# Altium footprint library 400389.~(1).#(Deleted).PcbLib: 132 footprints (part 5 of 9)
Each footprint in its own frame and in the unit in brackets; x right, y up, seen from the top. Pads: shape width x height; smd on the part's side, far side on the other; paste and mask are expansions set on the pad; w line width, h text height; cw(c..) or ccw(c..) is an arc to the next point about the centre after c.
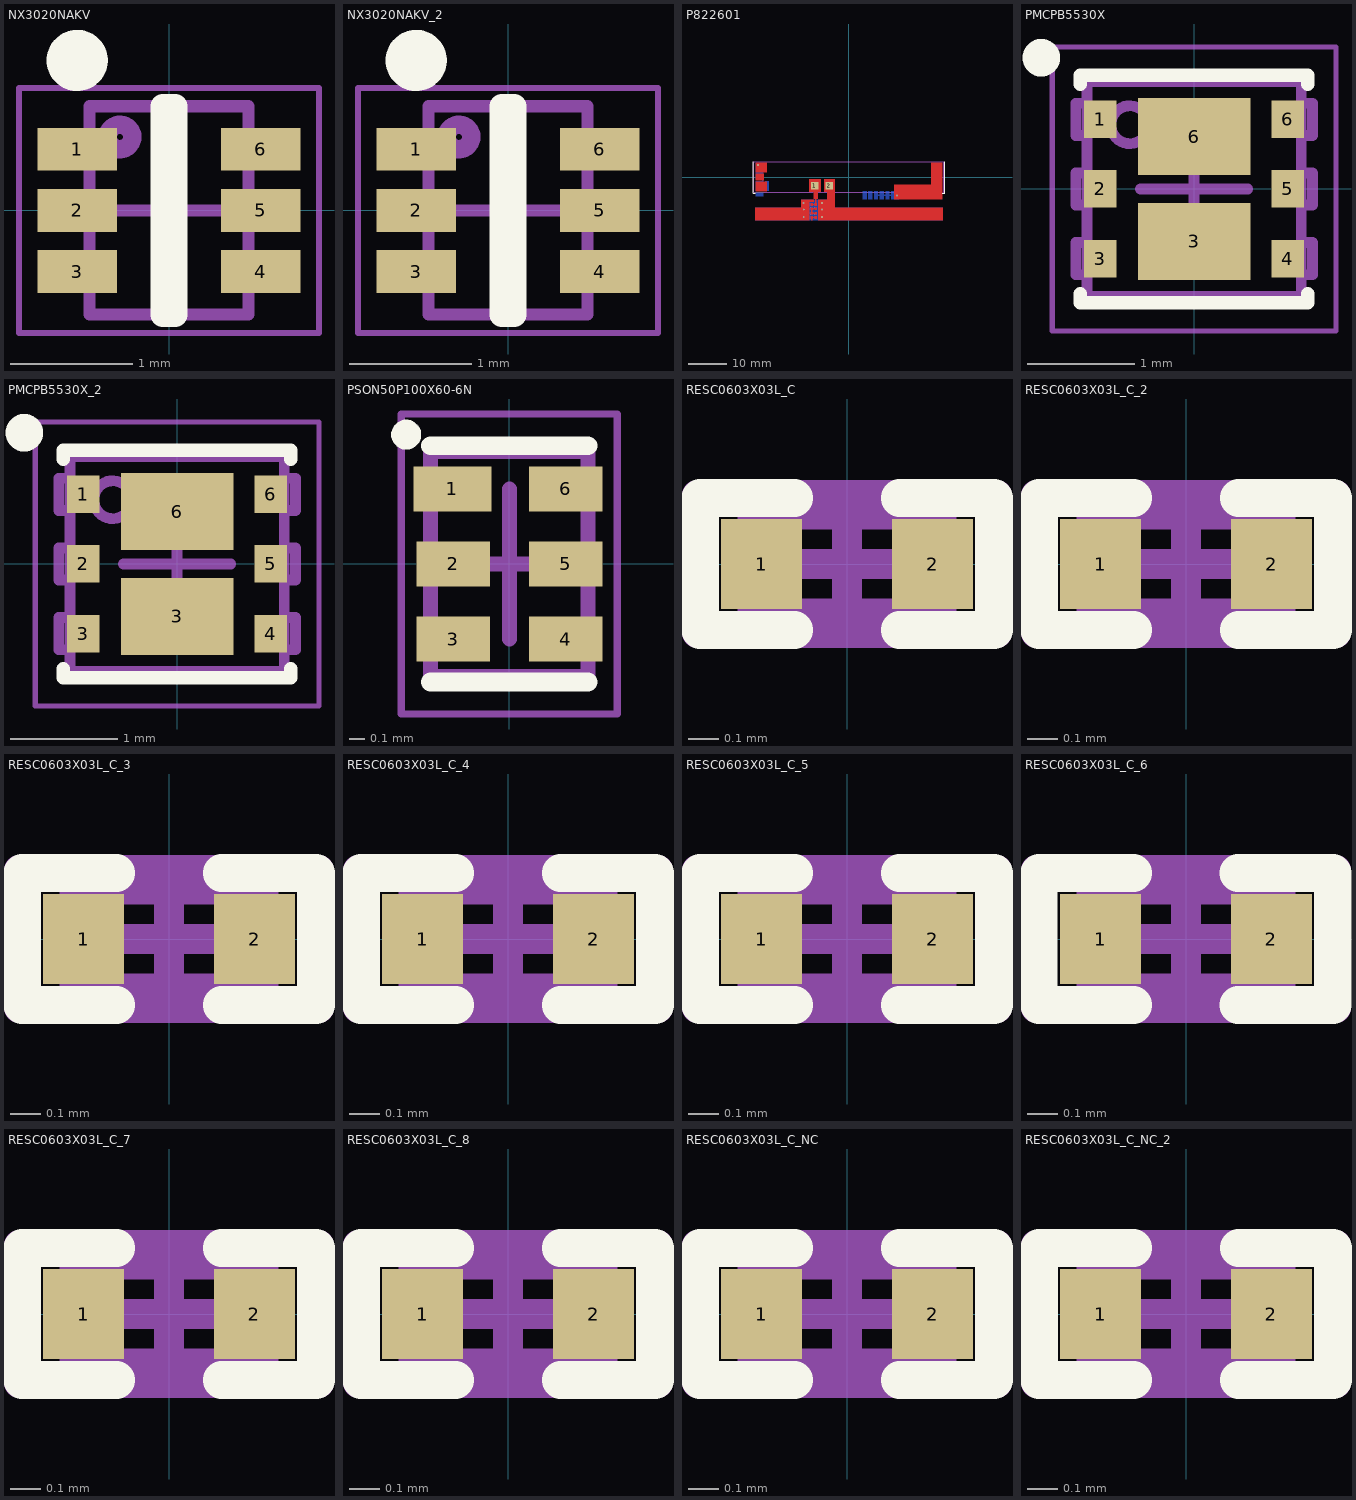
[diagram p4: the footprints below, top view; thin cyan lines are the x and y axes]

## NX3020NAKV [mm]
pads (6):
  rect 0.65x0.35 smd: 1(-0.75,0.5) 2(-0.75,0) 3(-0.75,-0.5) 4(0.75,-0.5) 5(0.75,0) 6(0.75,0.5)
Top Overlay:
  circle w0.25: c-0.75,1.225 r0.125
  lines w0.2: -0.05,-0.85 -0.05,0.85 0.05,0.85 0.05,-0.85 -0.05,-0.85
Mechanical 7:
  circle w0.15: c-0.4,0.6 r0.1
  lines w0.1: -0.65,-0.85 0.65,-0.85 0.65,0.85 -0.65,0.85 -0.65,-0.85
  text ".Designator" at 0,0 h0.3
Mechanical 13:
  lines w0.1: -0.65,-0.85 0.65,-0.85 0.65,0.85 -0.65,0.85 -0.65,-0.85
Mechanical 15:
  lines w0.05: -1.225,-1 1.225,-1 1.225,1 -1.225,1 -1.225,-1
  lines w0.1: -0.5,0 0.5,0 ; 0,-0.5 0,0.5
3D body "NX3020NAKV2.step": height 0.6, standoff 0, extent -0.8,-0.848 0.8,0.848

## NX3020NAKV_2 [mm]
pads (6):
  rect 0.65x0.35 smd: 1(-0.75,0.5) 2(-0.75,0) 3(-0.75,-0.5) 4(0.75,-0.5) 5(0.75,0) 6(0.75,0.5)
Top Overlay:
  circle w0.25: c-0.75,1.225 r0.125
  lines w0.2: -0.05,-0.85 0.05,-0.85 0.05,0.85 -0.05,0.85 -0.05,-0.85
Mechanical 7:
  circle w0.15: c-0.4,0.6 r0.1
  lines w0.1: -0.65,-0.85 -0.65,0.85 0.65,0.85 0.65,-0.85 -0.65,-0.85
  text ".Designator" at 0,0 h0.3
Mechanical 13:
  lines w0.1: -0.65,-0.85 -0.65,0.85 0.65,0.85 0.65,-0.85 -0.65,-0.85
Mechanical 15:
  lines w0.05: -1.225,-1 -1.225,1 1.225,1 1.225,-1 -1.225,-1
  lines w0.1: -0.5,0 0.5,0 ; 0,-0.5 0,0.5
3D body "NX3020NAKV2.step": height 0.6, standoff 0, extent -0.8,-0.848 0.8,0.848

## P822601 [mm]
pads (2):
  rect 2x2 smd: 1(-8.89,-2.286) 2(-5.08,-2.286)
via -11.886,-6.746 diameter 0.5 hole 0.25
via -7.05,-6.746 diameter 0.5 hole 0.25
via -23.85,3.254 diameter 0.5 hole 0.25
via 12.7,-4.796 diameter 0.5 hole 0.25
via -11.84,-8.55 diameter 0.5 hole 0.25
via -7.05,-8.55 diameter 0.5 hole 0.25
via -11.84,-10.466 diameter 0.5 hole 0.25
via -7.05,-10.466 diameter 0.5 hole 0.25
Top Layer:
  region: -8.45,-8.196 -8.95,-8.196 -8.95,-7.996 -8.45,-7.996
  region: -9.45,-8.196 -9.95,-8.196 -9.95,-7.996 -9.45,-7.996
  region: -8.45,-8.396 -9.95,-8.396 -9.95,-8.196 -8.45,-8.196
  region: -8.45,-8.596 -8.95,-8.596 -8.95,-8.396 -8.45,-8.396
  region: -9.45,-8.596 -9.95,-8.596 -9.95,-8.396 -9.45,-8.396
  region: -9.6,-9.196 -9.8,-9.196 -9.8,-8.596 -9.6,-8.596
  region: -8.45,-9.396 -8.95,-9.396 -8.95,-9.196 -8.45,-9.196
  region: -9.45,-9.396 -9.95,-9.396 -9.95,-9.196 -9.45,-9.196
  region: -8.45,-9.596 -9.95,-9.596 -9.95,-9.396 -8.45,-9.396
  region: -8.45,-9.796 -8.95,-9.796 -8.95,-9.596 -8.45,-9.596
  region: -9.45,-9.796 -9.95,-9.796 -9.95,-9.596 -9.45,-9.596
  region: -21.6,1.254 -24.5,1.254 -24.5,3.754 -21.6,3.754
  region: -22.4,-0.846 -24.5,-0.846 -24.5,0.854 -22.4,0.854
  region: -21.6,-3.746 -24.5,-3.746 -24.5,-1.246 -21.6,-1.246
  region: 24.6,-5.796 12.05,-5.796 12.05,-2.046 24.6,-2.046
  region: 24.6,-2.046 21.7,-2.046 21.7,3.754 24.6,3.754
  region: -3.67,-7.991 -8.05,-7.991 -8.05,-5.996 -3.67,-5.996
  region: -3.67,-5.996 -5.71,-5.996 -5.71,-3.826 -3.67,-3.826
  region: -3.67,-3.826 -6.399,-3.826 -6.4,-0.566 -3.67,-0.566
  region: -10.45,-7.996 -12.45,-7.996 -12.45,-6.496 -10.45,-6.496
  region: -9.2,-6.496 -12.45,-6.496 -12.45,-5.996 -9.2,-5.996
  region: -9.45,-7.496 -9.95,-7.496 -9.95,-7.296 -9.45,-7.296
  region: -8.45,-7.496 -8.95,-7.496 -8.95,-7.296 -8.45,-7.296
  region: -8.45,-7.296 -9.95,-7.296 -9.95,-7.096 -8.45,-7.096
  region: -9.45,-7.096 -9.95,-7.096 -9.95,-6.896 -9.45,-6.896
  region: -8.45,-7.096 -8.95,-7.096 -8.95,-6.896 -8.45,-6.896
  region: -8.6,-6.896 -8.8,-6.896 -8.8,-5.696 -8.6,-5.696
  region: -8.2,-5.696 -9.2,-5.696 -9.2,-3.796 -8.2,-3.796
  region: -7.3,-3.796 -10.4,-3.796 -10.4,-0.596 -7.3,-0.596
  region: -9.6,-11.296 -9.8,-11.296 -9.8,-10.896 -9.6,-10.896
  region: -9.45,-10.896 -9.95,-10.896 -9.95,-10.696 -9.45,-10.696
  region: -8.45,-10.896 -8.95,-10.896 -8.95,-10.696 -8.45,-10.696
  region: -8.45,-10.696 -9.95,-10.696 -9.95,-10.496 -8.45,-10.496
  region: -9.45,-10.496 -9.95,-10.496 -9.95,-10.296 -9.45,-10.296
  region: -8.45,-10.496 -8.95,-10.496 -8.95,-10.296 -8.45,-10.296
  region: 24.75,-11.296 -8.05,-11.296 -8.05,-8.001 24.75,-8.001
  region: -10.45,-11.296 -24.65,-11.296 -24.65,-7.996 -10.45,-7.996
Bottom Layer:
  region: -22.5,-3.546 -24.5,-3.546 -24.5,-2.546 -22.5,-2.546
  region: -24.196,-2.546 -24.5,-2.546 -24.5,-2.046 -24.196,-2.046
  region: -22.5,-2.046 -24.5,-2.046 -24.5,-1.046 -22.5,-1.046
  region: -22.5,-1.046 -22.8,-1.046 -22.8,-0.546 -22.5,-0.546
  region: -22.5,-0.546 -24.5,-0.546 -24.5,3.754 -22.5,3.754
  region: -21,-3.546 -22,-3.546 -22,-1.046 -21,-1.046
  region: -22.5,-5.046 -24.5,-5.046 -24.5,-4.046 -22.5,-4.046
  region: 7.7,-5.796 6.7,-5.796 6.7,-4.896 7.7,-4.896
  region: 9.2,-5.796 8.2,-5.796 8.2,-4.896 9.2,-4.896
  region: 10.7,-5.796 9.7,-5.796 9.7,-4.896 10.7,-4.896
  region: 13.2,-5.796 11.2,-5.796 11.2,-4.896 13.2,-4.896
  region: 13.2,-4.896 6.7,-4.896 6.7,-4.596 13.2,-4.596
  region: 7.7,-4.596 6.7,-4.596 6.7,-3.746 7.7,-3.746
  region: 9.2,-4.596 8.2,-4.596 8.2,-3.746 9.2,-3.746
  region: 10.7,-4.596 9.7,-4.596 9.7,-3.746 10.7,-3.746
  region: 13.2,-4.596 11.2,-4.596 11.2,-3.746 13.2,-3.746
  region: 6.2,-5.796 5.2,-5.796 5.2,-3.746 6.2,-3.746
  region: 4.7,-5.796 3.7,-5.796 3.7,-3.746 4.7,-3.746
  region: -3.86,-7.996 -12.45,-7.996 -12.45,-5.996 -3.86,-5.996
  region: 24.752,-11.296 -24.648,-11.296 -24.65,-7.996 24.75,-7.996
Top Overlay:
  lines w0.2: -25.2,4.05 -25.2,-4.25 -24.575,-4.25 ; 24.675,-4.25 25.3,-4.25 25.3,4.05
Top Paste:
  region: 23.5,-3.746 21.7,-3.746 21.7,-2.546 23.5,-2.546
  region: 24.6,-2.546 21.7,-2.546 21.7,-0.546 24.6,-0.546
  region: 23.5,-0.546 21.7,-0.546 21.7,0.554 23.5,0.554
  region: 24.6,0.554 21.7,0.554 21.7,2.554 24.6,2.554
  region: 23.5,2.554 21.7,2.554 21.7,3.754 23.5,3.754
  region: 16.75,-3.746 14.35,-3.746 14.35,-2.546 16.75,-2.546
  region: -21.6,1.254 -24.5,1.254 -24.5,2.654 -21.6,2.654
  region: -21.6,2.654 -23.25,2.654 -23.25,3.737 -21.6,3.737
  region: -22.4,-0.846 -24.5,-0.846 -24.5,0.854 -22.4,0.854
  region: -21.6,-3.746 -24.5,-3.746 -24.5,-1.246 -21.6,-1.246
Top Solder:
  region: -3.67,-3.746 -6.4,-3.746 -6.4,-0.546 -3.67,-0.546
  region: -7.3,-3.746 -10.4,-3.746 -10.4,-0.596 -7.3,-0.596
  region: 16.75,-3.746 14.35,-3.746 14.35,-2.546 16.75,-2.546
  region: 23.5,2.554 21.7,2.554 21.7,3.754 23.5,3.754
  region: 24.6,0.554 21.7,0.554 21.7,2.554 24.6,2.554
  region: 23.5,-0.546 21.7,-0.546 21.7,0.554 23.5,0.554
  region: 24.6,-2.546 21.7,-2.546 21.7,-0.546 24.6,-0.546
  region: 23.5,-3.746 21.7,-3.746 21.7,-2.546 23.5,-2.546
  region: -21.6,-3.746 -24.5,-3.746 -24.5,-1.246 -21.6,-1.246
  region: -22.4,-0.846 -24.5,-0.846 -24.5,0.854 -22.4,0.854
  region: -21.6,2.654 -23.25,2.654 -23.25,3.737 -21.6,3.737
  region: -21.6,1.254 -24.5,1.254 -24.5,2.654 -21.6,2.654
Bottom Solder:
  region: -22.5,-2.046 -23.025,-2.046 -23.025,-1.446 -22.5,-1.446
  region: -21.48,-2.046 -22,-2.046 -22,-1.446 -21.48,-1.446
  region: -21.48,-3.146 -22,-3.146 -22,-2.546 -21.48,-2.546
  region: -22.5,-3.146 -23.025,-3.146 -23.025,-2.546 -22.5,-2.546
  region: -23.975,-1.646 -24.5,-1.646 -24.5,-1.046 -23.975,-1.046
  region: -23.975,-3.546 -24.5,-3.546 -24.5,-2.957 -23.975,-2.957
  region: -23.975,-4.646 -24.5,-4.646 -24.5,-4.046 -23.975,-4.046
  region: -23.975,-0.546 -24.5,-0.546 -24.5,0.054 -23.975,0.054
  region: 5.8,-5.796 5.2,-5.796 5.2,-5.276 5.8,-5.276
  region: 4.7,-5.796 4.1,-5.796 4.1,-5.276 4.7,-5.276
  region: 6.2,-4.266 5.6,-4.266 5.6,-3.746 6.2,-3.746
  region: 7.3,-4.266 6.7,-4.266 6.7,-3.746 7.3,-3.746
  region: 9.2,-4.271 8.6,-4.271 8.6,-3.746 9.2,-3.746
  region: 10.3,-4.271 9.7,-4.271 9.7,-3.746 10.3,-3.746
  region: 10.7,-5.796 10.1,-5.796 10.1,-5.271 10.7,-5.271
  region: 8.8,-5.796 8.2,-5.796 8.2,-5.271 8.8,-5.271
  region: 7.7,-5.796 7.1,-5.796 7.1,-5.271 7.7,-5.271
  region: 11.8,-5.796 11.2,-5.796 11.2,-5.271 11.8,-5.271
Mechanical 5:
  region: -10.45,-10.896 -10.97,-10.896 -10.97,-10.296 -10.45,-10.296
  region: -10.45,-9.796 -10.97,-9.796 -10.97,-9.196 -10.45,-9.196
  region: -10.45,-7.496 -10.97,-7.496 -10.97,-6.896 -10.45,-6.896
  region: -9.45,-10.896 -9.95,-10.896 -9.95,-10.296 -9.45,-10.296
  region: -8.45,-10.896 -8.95,-10.896 -8.95,-10.296 -8.45,-10.296
  region: -8.45,-9.796 -8.95,-9.796 -8.95,-9.196 -8.45,-9.196
  region: -9.45,-9.785 -9.95,-9.785 -9.95,-9.196 -9.45,-9.196
  region: -8.45,-7.496 -8.95,-7.496 -8.95,-6.896 -8.45,-6.896
  region: -9.45,-7.496 -9.95,-7.496 -9.95,-6.896 -9.45,-6.896
  region: -10.45,-8.596 -10.97,-8.596 -10.97,-7.996 -10.45,-7.996
  region: -9.45,-8.596 -9.95,-8.596 -9.95,-7.996 -9.45,-7.996
  region: -8.45,-8.596 -8.95,-8.596 -8.95,-7.996 -8.45,-7.996
Mechanical 7:
  lines w0.1: -24.95,-4.005 -24.95,4.004 25.05,4.004 25.05,-4.005 -24.95,-4.005
Mechanical 15:
  lines w0.254: -24.95,-4.005 25.05,-4.005 25.05,4.004 -24.95,4.004 -24.95,-4.005
Multi-Layer:
  pour cut-out: -39.95,5.08 39.05,5.08 39.05,-7.996 -39.95,-7.996
3D body: height 3.2, standoff 0, extent -24.95,-4 25.05,4

## PMCPB5530X [mm]
pads (8):
  rect 0.3x0.35 smd mask+0.05: 1(-0.875,0.65) 2(-0.875,0) 3(-0.875,-0.65) 4(0.875,-0.65) 5(0.875,0) 6(0.875,0.65)
  rect 1.05x0.72 smd mask+0.05: 3(0,-0.49) 6(0,0.49)
Top Overlay:
  circle w0.25: c-1.425,1.225 r0.05
  lines w0.125: -1.063,-0.978 -1.063,-1.063 1.063,-1.063 1.063,-0.978 ; -1.063,0.978 -1.063,1.063 1.063,1.063 1.063,0.978
Mechanical 7:
  circle w0.1: c-0.6,0.6 r0.177
  lines w0.1: -1,-0.8 -1.105,-0.8 -1.105,-0.5 -1,-0.5 ; -1,-0.15 -1.105,-0.15 -1.105,0.15 -1,0.15 ; -1,0.5 -1.105,0.5 -1.105,0.8 -1,0.8 ; 1,-0.8 1.105,-0.8 1.105,-0.5 1,-0.5 ; 1,-0.15 1.105,-0.15 1.105,0.15 1,0.15 ; 1,0.5 1.105,0.5 1.105,0.8 1,0.8 ; -1,-1 1,-1 1,1 -1,1 -1,-1
  text ".Designator" at -0.6,-0.2 h0.38
Mechanical 15:
  lines w0.05: -1.325,-1.325 1.325,-1.325 1.325,1.325 -1.325,1.325 -1.325,-1.325
  lines w0.1: -0.5,0 0.5,0 ; 0,-0.5 0,0.5
3D body "QFN65P200X200X65-6N.step": height 0.65, standoff 0, extent -1.051,-1.05 1.051,1.05

## PMCPB5530X_2 [mm]
pads (8):
  rect 0.3x0.35 smd mask+0.05: 1(-0.875,0.65) 2(-0.875,0) 3(-0.875,-0.65) 4(0.875,-0.65) 5(0.875,0) 6(0.875,0.65)
  rect 1.05x0.72 smd mask+0.05: 3(0,-0.49) 6(0,0.49)
Top Overlay:
  circle w0.25: c-1.425,1.225 r0.05
  lines w0.125: -1.063,-0.978 -1.063,-1.063 1.063,-1.063 1.063,-0.978 ; -1.063,0.978 -1.063,1.063 1.063,1.063 1.063,0.978
Mechanical 7:
  circle w0.1: c-0.6,0.6 r0.177
  lines w0.1: -1,-0.8 -1.105,-0.8 -1.105,-0.5 -1,-0.5 ; -1,-0.15 -1.105,-0.15 -1.105,0.15 -1,0.15 ; -1,0.5 -1.105,0.5 -1.105,0.8 -1,0.8 ; 1,-0.8 1.105,-0.8 1.105,-0.5 1,-0.5 ; 1,-0.15 1.105,-0.15 1.105,0.15 1,0.15 ; 1,0.5 1.105,0.5 1.105,0.8 1,0.8 ; -1,-1 1,-1 1,1 -1,1 -1,-1
  text ".Designator" at -0.6,-0.2 h0.38
Mechanical 15:
  lines w0.05: -1.325,-1.325 1.325,-1.325 1.325,1.325 -1.325,1.325 -1.325,-1.325
  lines w0.1: -0.5,0 0.5,0 ; 0,-0.5 0,0.5
3D body "QFN65P200X200X65-6N.step": height 0.65, standoff 0, extent -1.051,-1.05 1.051,1.05

## PSON50P100X60-6N [mm]
pads (6):
  rect 0.52x0.3 smd mask+0.05: 1(-0.38,0.5)
  rect 0.49x0.3 smd mask+0.05: 2(-0.375,0) 3(-0.375,-0.5) 4(0.375,-0.5) 5(0.375,0) 6(0.375,0.5)
Top Overlay:
  circle w0.1: c-0.687,0.862 r0.05
  lines w0.125: -0.525,-0.787 0.525,-0.787 ; -0.525,0.787 0.525,0.787
Mechanical 7:
  lines w0.1: -0.525,-0.75 -0.525,0.75 0.525,0.75 0.525,-0.75 -0.525,-0.75
Mechanical 15:
  lines w0.05: -0.72,-1 -0.72,1 0.72,1 0.72,-1 -0.72,-1
  lines w0.1: -0.5,0 0.5,0 ; 0,-0.5 0,0.5
3D body "PSON50P100X60-6N.step": height 0.6, standoff 0, extent -0.526,-0.75 0.526,0.75

## RESC0603X03L_C [mm]
pads (2):
  rect 0.27x0.3 smd: 1(-0.285,0) 2(0.285,0)
Top Overlay:
  lines w0.125: -0.175,-0.22 -0.49,-0.22 -0.49,0.22 -0.175,0.22 ; 0.175,-0.22 0.49,-0.22 0.49,0.22 0.175,0.22
Mechanical 7:
  lines w0.1: -0.315,-0.165 0.315,-0.165 0.315,0.165 -0.315,0.165 -0.315,-0.165
  text ".Designator" at -0.306,0.268 h0.3
Mechanical 15:
  lines w0.1: -0.165,0 0.165,0 ; 0,-0.165 0,0.165 ; -0.5,-0.23 0.5,-0.23 0.5,0.23 -0.5,0.23 -0.5,-0.23
3D body "User Library-res0201-1.step": height 0.23, standoff 0, extent -0.3,-0.15 0.3,0.15

## RESC0603X03L_C_2 [mm]
pads (2):
  rect 0.27x0.3 smd: 1(-0.285,0) 2(0.285,0)
Top Overlay:
  lines w0.125: -0.175,-0.22 -0.49,-0.22 -0.49,0.22 -0.175,0.22 ; 0.175,-0.22 0.49,-0.22 0.49,0.22 0.175,0.22
Mechanical 7:
  lines w0.1: -0.315,-0.165 -0.315,0.165 0.315,0.165 0.315,-0.165 -0.315,-0.165
  text ".Designator" at -0.306,0.268 h0.3
Mechanical 15:
  lines w0.1: -0.165,0 0.165,0 ; 0,-0.165 0,0.165 ; -0.5,-0.23 -0.5,0.23 0.5,0.23 0.5,-0.23 -0.5,-0.23
3D body "User Library-res0201-1.step": height 0.23, standoff 0, extent -0.3,-0.15 0.3,0.15

## RESC0603X03L_C_3 [mm]
pads (2):
  rect 0.27x0.3 smd: 1(-0.285,0) 2(0.285,0)
Top Overlay:
  lines w0.125: -0.175,-0.22 -0.49,-0.22 -0.49,0.22 -0.175,0.22 ; 0.175,-0.22 0.49,-0.22 0.49,0.22 0.175,0.22
Mechanical 7:
  lines w0.1: -0.315,-0.165 0.315,-0.165 0.315,0.165 -0.315,0.165 -0.315,-0.165
  text ".Designator" at -0.306,0.268 h0.3
Mechanical 15:
  lines w0.1: -0.165,0 0.165,0 ; 0,-0.165 0,0.165 ; -0.5,-0.23 0.5,-0.23 0.5,0.23 -0.5,0.23 -0.5,-0.23
3D body "User Library-res0201-1.step": height 0.23, standoff 0, extent -0.3,-0.15 0.3,0.15

## RESC0603X03L_C_4 [mm]
pads (2):
  rect 0.27x0.3 smd: 1(-0.285,0) 2(0.285,0)
Top Overlay:
  lines w0.125: -0.175,-0.22 -0.49,-0.22 -0.49,0.22 -0.175,0.22 ; 0.175,-0.22 0.49,-0.22 0.49,0.22 0.175,0.22
Mechanical 7:
  lines w0.1: -0.315,-0.165 0.315,-0.165 0.315,0.165 -0.315,0.165 -0.315,-0.165
  text ".Designator" at -0.306,0.268 h0.3
Mechanical 15:
  lines w0.1: -0.165,0 0.165,0 ; 0,-0.165 0,0.165 ; -0.5,-0.23 0.5,-0.23 0.5,0.23 -0.5,0.23 -0.5,-0.23
3D body "User Library-res0201-1.step": height 0.23, standoff 0, extent -0.3,-0.15 0.3,0.15

## RESC0603X03L_C_5 [mm]
pads (2):
  rect 0.27x0.3 smd: 1(-0.285,0) 2(0.285,0)
Top Overlay:
  lines w0.125: -0.175,-0.22 -0.49,-0.22 -0.49,0.22 -0.175,0.22 ; 0.175,-0.22 0.49,-0.22 0.49,0.22 0.175,0.22
Mechanical 7:
  lines w0.1: -0.315,-0.165 0.315,-0.165 0.315,0.165 -0.315,0.165 -0.315,-0.165
  text ".Designator" at -0.306,0.268 h0.3
Mechanical 15:
  lines w0.1: -0.165,0 0.165,0 ; 0,-0.165 0,0.165 ; -0.5,-0.23 0.5,-0.23 0.5,0.23 -0.5,0.23 -0.5,-0.23
3D body "User Library-res0201-1.step": height 0.23, standoff 0, extent -0.3,-0.15 0.3,0.15

## RESC0603X03L_C_6 [mm]
pads (2):
  rect 0.27x0.3 smd: 1(-0.285,0) 2(0.285,0)
Top Overlay:
  lines w0.125: -0.175,-0.22 -0.49,-0.22 -0.49,0.22 -0.175,0.22 ; 0.175,-0.22 0.49,-0.22 0.49,0.22 0.175,0.22
Mechanical 7:
  lines w0.1: -0.315,-0.165 0.315,-0.165 0.315,0.165 -0.315,0.165 -0.315,-0.165
  text ".Designator" at -0.306,0.268 h0.3
Mechanical 15:
  lines w0.1: -0.165,0 0.165,0 ; 0,-0.165 0,0.165 ; -0.5,-0.23 0.5,-0.23 0.5,0.23 -0.5,0.23 -0.5,-0.23
3D body "User Library-res0201-1.step": height 0.23, standoff 0, extent -0.3,-0.15 0.3,0.15

## RESC0603X03L_C_7 [mm]
pads (2):
  rect 0.27x0.3 smd: 1(-0.285,0) 2(0.285,0)
Top Overlay:
  lines w0.125: -0.175,-0.22 -0.49,-0.22 -0.49,0.22 -0.175,0.22 ; 0.175,-0.22 0.49,-0.22 0.49,0.22 0.175,0.22
Mechanical 7:
  lines w0.1: -0.315,-0.165 0.315,-0.165 0.315,0.165 -0.315,0.165 -0.315,-0.165
  text ".Designator" at -0.306,0.268 h0.3
Mechanical 15:
  lines w0.1: -0.165,0 0.165,0 ; 0,-0.165 0,0.165 ; -0.5,-0.23 0.5,-0.23 0.5,0.23 -0.5,0.23 -0.5,-0.23
3D body "User Library-res0201-1.step": height 0.23, standoff 0, extent -0.3,-0.15 0.3,0.15

## RESC0603X03L_C_8 [mm]
pads (2):
  rect 0.27x0.3 smd: 1(-0.285,0) 2(0.285,0)
Top Overlay:
  lines w0.125: -0.175,-0.22 -0.49,-0.22 -0.49,0.22 -0.175,0.22 ; 0.175,-0.22 0.49,-0.22 0.49,0.22 0.175,0.22
Mechanical 7:
  lines w0.1: -0.315,-0.165 0.315,-0.165 0.315,0.165 -0.315,0.165 -0.315,-0.165
  text ".Designator" at -0.306,0.268 h0.3
Mechanical 15:
  lines w0.1: -0.165,0 0.165,0 ; 0,-0.165 0,0.165 ; -0.5,-0.23 -0.5,0.23 0.5,0.23 0.5,-0.23 -0.5,-0.23
3D body "User Library-res0201-1.step": height 0.23, standoff 0, extent -0.3,-0.15 0.3,0.15

## RESC0603X03L_C_NC [mm]
pads (2):
  rect 0.27x0.3 smd: 1(-0.285,0) 2(0.285,0)
Top Overlay:
  lines w0.125: -0.175,-0.22 -0.49,-0.22 -0.49,0.22 -0.175,0.22 ; 0.175,-0.22 0.49,-0.22 0.49,0.22 0.175,0.22
Mechanical 7:
  lines w0.1: -0.315,-0.165 -0.315,0.165 0.315,0.165 0.315,-0.165 -0.315,-0.165
  text ".Designator" at -0.306,0.268 h0.3
Mechanical 15:
  lines w0.1: -0.165,0 0.165,0 ; 0,-0.165 0,0.165 ; -0.5,-0.23 -0.5,0.23 0.5,0.23 0.5,-0.23 -0.5,-0.23

## RESC0603X03L_C_NC_2 [mm]
pads (2):
  rect 0.27x0.3 smd: 1(-0.285,0) 2(0.285,0)
Top Overlay:
  lines w0.125: -0.175,-0.22 -0.49,-0.22 -0.49,0.22 -0.175,0.22 ; 0.175,-0.22 0.49,-0.22 0.49,0.22 0.175,0.22
Mechanical 7:
  lines w0.1: -0.315,-0.165 -0.315,0.165 0.315,0.165 0.315,-0.165 -0.315,-0.165
  text ".Designator" at -0.306,0.268 h0.3
Mechanical 15:
  lines w0.1: -0.165,0 0.165,0 ; 0,-0.165 0,0.165 ; -0.5,-0.23 -0.5,0.23 0.5,0.23 0.5,-0.23 -0.5,-0.23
